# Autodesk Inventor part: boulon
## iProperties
Author: ajt
Created: 2001-10
Part Number: boulon
Material: Par défaut
Document SubType Name: Modélisation
Designer: ajt
Control State: 0
Master: False
Checked Out: False
PropertySet Name: Design Tracking Control
Shininess: 21.0
PropertySet Name: _Private Model Information
Length Units: 11269
Angle Units: 11283
Time Units: 11279
Mass Units: 11290
Length Display Precision: 3
Angle Display Precision: 2
Compacted: False
Density: 0.0
Volumn: 0.0
Area: 0.0
PropertySet Name: Model Information
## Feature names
1. Extrusion1
2. Extrusion2
3. Chanfrein1 [Chamfer]
